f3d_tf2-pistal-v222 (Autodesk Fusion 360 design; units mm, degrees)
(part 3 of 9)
sketch "Sketch46" plane through (0, 19.0955, 0) normal (0, -1, 0) x axis (1, 0, 0)
  line L1 (17.9977, -3.324) -> (-17.9973, -3.324)
  line L2 (17.9977, -3.324) -> (19.9977, 0.985)
  line L3 (19.9977, 30) -> (19.9977, 0.985)
  line L4 (-19.9973, 30) -> (19.9977, 30)
  line L5 (-19.9973, 0.985) -> (-19.9973, 30)
  line L6 (-19.9973, 0.985) -> (-17.9973, -3.324)
  line L7 (-15, 25) -> (15, 25)
  line L8 (-15, -25) -> (-15, 25)
  line L9 (15, -25) -> (-15, -25)
  line L10 (15, 25) -> (15, -25)
  line L11 (-15, -25) -> (15, 25)
  line L12 (15, -25) -> (-15, 25)
  line L13 (-18.3388, 10) -> (-9.0048, 10)
  line L14 (-19.9973, 10) -> (-18.3388, 10)
  line L15 (-19.9973, 10) -> (-19.9977, 10)
  line L16 (-13, 10) -> (-19.9977, 10)
  line L17 (-9.0048, 10) -> (-13, 10)
  line L18 (40, 10) -> (-30, 10)
  point P12 (0, 0)
  point P1 (0, 0)
  horizontal L7
  perpendicular L7 L8
  parallel L7 L9
  parallel L8 L10
  coincident L11 P12
  coincident L12 P12
  coincident P1 P12
  perpendicular L5 L18
extrude "Extrude43" cut sketch "Sketch46" profile of L3 L4 L5 L7 L8 L10 L13 L14 L16 L18 against normal blind 125.217
delete_face "DeleteFace39"
extrude "Extrude44" add of existing geometry blind 3
fillet "Fillet54" radius 12
move "Move19" RotateAngle 30
sketch "Sketch47" plane through (16.9981, 0, 0) normal (1, 0, 0) x axis (0, 1, 0)
  line L1 (175.396, -38.6118) -> (173.8866, -33.2249)
  curve K1 (175.4894, -38.6471) -> (175.396, -38.6118)
  curve K2 (175.2557, -36.9411) -> (175.8993, -38.2372)
  curve K3 (175.7658, -36.3594) -> (175.2557, -36.9411)
  curve K4 (177.1348, -36.8283) -> (175.7658, -36.3594)
  curve K5 (176.6805, -35.1674) -> (177.4877, -36.3684)
  curve K6 (177.1103, -34.5242) -> (176.6805, -35.1674)
  curve K7 (178.5288, -34.8104) -> (177.1103, -34.5242)
  curve K8 (177.8615, -33.223) -> (178.8186, -34.3083)
  curve K9 (178.2037, -32.5291) -> (177.8615, -33.223)
  curve K10 (179.6474, -32.6277) -> (178.2037, -32.5291)
  curve K11 (178.7787, -31.141) -> (179.8693, -32.0922)
  curve K12 (179.0274, -30.4084) -> (178.7787, -31.141)
  curve K13 (180.4716, -30.3177) -> (179.0274, -30.4084)
  curve K14 (179.4162, -28.9571) -> (180.6216, -29.7578)
  curve K15 (179.5672, -28.1983) -> (179.4162, -28.9571)
  curve K16 (180.9872, -27.9199) -> (179.5672, -28.1983)
  curve K17 (179.7633, -26.7087) -> (181.0629, -27.3452)
  curve K18 (179.8139, -25.9367) -> (179.7633, -26.7087)
  curve K19 (181.1854, -25.4753) -> (179.8139, -25.9367)
  curve K20 (179.8139, -24.4342) -> (181.1854, -24.8956)
  curve K21 (179.7633, -23.6622) -> (179.8139, -24.4342)
  curve K22 (181.0629, -23.0257) -> (179.7633, -23.6622)
  curve K23 (179.5672, -22.1726) -> (180.9872, -22.451)
  curve K24 (179.4162, -21.4138) -> (179.5672, -22.1726)
  curve K25 (180.6216, -20.6131) -> (179.4162, -21.4138)
  curve K26 (179.0274, -19.9625) -> (180.4716, -20.0532)
  curve K27 (178.7787, -19.2299) -> (179.0274, -19.9625)
  curve K28 (179.8693, -18.2788) -> (178.7787, -19.2299)
  curve K29 (178.2037, -17.8418) -> (179.6474, -17.7432)
  curve K30 (177.8615, -17.148) -> (178.2037, -17.8418)
  curve K31 (178.8186, -16.0626) -> (177.8615, -17.148)
  curve K32 (177.1103, -15.8468) -> (178.5288, -15.5606)
  curve K33 (176.6805, -15.2035) -> (177.1103, -15.8468)
  curve K34 (177.4877, -14.0025) -> (176.6805, -15.2035)
  curve K35 (175.7658, -14.0115) -> (177.1348, -13.5426)
  curve K36 (175.2557, -13.4298) -> (175.7658, -14.0115)
  curve K37 (175.8993, -12.1337) -> (175.2557, -13.4298)
  curve K38 (174.1933, -12.3674) -> (175.4894, -11.7239)
  curve K39 (173.6116, -11.8573) -> (174.1933, -12.3674)
  curve K40 (174.0805, -10.4883) -> (173.6116, -11.8573)
  curve K41 (172.4196, -10.9427) -> (173.6206, -10.1354)
  curve K42 (171.9212, -10.9679) -> (172.4196, -10.9427)
  line L2 (170.1162, -13.6698) -> (171.9212, -10.9679)
  line L3 (174.9197, -19.1688) -> (177.7876, -17.6663)
  arc A1 centre (162.4377, -25.1855) radius 18.75 clockwise from (175.8993, -38.2372) to (175.4894, -38.6471)
  arc A2 centre (162.4377, -25.1855) radius 18.75 clockwise from (177.4877, -36.3684) to (177.1348, -36.8283)
  arc A3 centre (162.4377, -25.1855) radius 18.75 clockwise from (178.8186, -34.3083) to (178.5288, -34.8104)
  arc A4 centre (162.4377, -25.1855) radius 18.75 clockwise from (179.8693, -32.0922) to (179.6474, -32.6277)
  arc A5 centre (162.4377, -25.1855) radius 18.75 clockwise from (180.6216, -29.7578) to (180.4716, -30.3177)
  arc A6 centre (162.4377, -25.1855) radius 18.75 clockwise from (181.0629, -27.3452) to (180.9872, -27.9199)
  arc A7 centre (162.4377, -25.1855) radius 18.75 clockwise from (181.1854, -24.8956) to (181.1854, -25.4753)
  arc A8 centre (162.4377, -25.1855) radius 18.75 clockwise from (180.9872, -22.451) to (181.0629, -23.0257)
  arc A9 centre (162.4377, -25.1855) radius 18.75 clockwise from (180.4716, -20.0532) to (180.6216, -20.6131)
  arc A10 centre (162.4377, -25.1855) radius 18.75 clockwise from (179.6474, -17.7432) to (179.8693, -18.2788)
  arc A11 centre (162.4377, -25.1855) radius 18.75 clockwise from (178.5288, -15.5606) to (178.8186, -16.0626)
  arc A12 centre (162.4377, -25.1855) radius 18.75 clockwise from (177.1348, -13.5426) to (177.4877, -14.0025)
  arc A13 centre (162.4377, -25.1855) radius 18.75 clockwise from (175.4894, -11.7239) to (175.8993, -12.1337)
  arc A14 centre (162.4377, -25.1855) radius 18.75 clockwise from (173.6206, -10.1354) to (174.0805, -10.4883)
  arc A15 centre (162.3398, -25.3102) radius 13.999 clockwise from (170.1162, -13.6698) to (173.8866, -33.2249)
  point P63 (177.7876, -17.6663)
  point P64 (174.9197, -19.1688)
  coincident K30 P63
  coincident A15 P64
extrude "Extrude45" new body sketch "Sketch47" profile of K30 K31 A11 K32 K33 K34 A12 K35 K36 K37 A13 K38 K39 K40 A14 K41 K42 L2 A15 L3 against normal blind 4
mirror "Mirror16" mirrorStitchTolerance 0.1
combine "Combine40"
fillet "Fillet55" radius 2
revolve "Revolve1" AlongAngle 30
revolve "Revolve2" AlongAngle 30
move "Move20" RotateAngle -30
sketch "Circle" plane through (16.7981, 0, 0) normal (1, 0, 0) x axis (0, 1, 0)
  line L1 (189.7947, -21.9467) -> (189.6413, -21.8116)
  curve K1 (190.953, -22.2857) -> (189.7947, -21.9467)
  curve K2 (190.5246, -20.9044) -> (191.2393, -21.8768)
  line L2 (190.3451, -20.8065) -> (190.5246, -20.9044)
  line L3 (190.9023, -20.0459) -> (190.7088, -19.9798)
  curve K3 (192.1021, -19.9159) -> (190.9023, -20.0459)
  curve K4 (191.1777, -18.8037) -> (192.2101, -19.4286)
  line L4 (190.9744, -18.7819) -> (191.1777, -18.8037)
  line L5 (191.1981, -17.866) -> (190.9941, -17.879)
  curve K5 (192.2569, -17.2868) -> (191.1981, -17.866)
  curve K6 (190.9772, -16.6129) -> (192.1702, -16.7952)
  line L6 (190.7811, -16.6706) -> (190.9772, -16.6129)
  line L7 (190.6373, -15.7388) -> (190.4537, -15.8288)
  curve K7 (191.3937, -14.7985) -> (190.6373, -15.7388)
  curve K8 (189.9536, -14.6657) -> (191.1255, -14.3775)
  line L8 (189.7944, -14.794) -> (189.9536, -14.6657)
  line L9 (189.305, -13.9882) -> (189.1699, -14.1416)
  curve K9 (189.6441, -12.8299) -> (189.305, -13.9882)
  curve K10 (188.2628, -13.2584) -> (189.2352, -12.5436)
  line L10 (188.1648, -13.4378) -> (188.2628, -13.2584)
  line L11 (187.4043, -12.8806) -> (187.3382, -13.0741)
  curve K11 (187.2743, -11.6808) -> (187.4043, -12.8806)
  curve K12 (186.162, -12.6052) -> (186.7869, -11.5728)
  line L12 (186.1402, -12.8085) -> (186.162, -12.6052)
  line L13 (185.2244, -12.5848) -> (185.2373, -12.7888)
  curve K13 (184.6451, -11.526) -> (185.2244, -12.5848)
  curve K14 (183.9713, -12.8057) -> (184.1535, -11.6127)
  line L14 (184.0289, -13.0019) -> (183.9713, -12.8057)
  line L15 (183.0972, -13.1457) -> (183.1872, -13.3292)
  curve K15 (182.1568, -12.3892) -> (183.0972, -13.1457)
  curve K16 (182.024, -13.8293) -> (181.7358, -12.6574)
  line L16 (182.1523, -13.9885) -> (182.024, -13.8293)
  line L17 (181.3465, -14.4779) -> (181.5, -14.613)
  curve K17 (180.1883, -14.1388) -> (181.3465, -14.4779)
  curve K18 (180.6167, -15.5202) -> (179.902, -14.5477)
  line L18 (180.7962, -15.6181) -> (180.6167, -15.5202)
  line L19 (180.239, -16.3786) -> (180.4324, -16.4448)
  curve K19 (179.0392, -16.5087) -> (180.239, -16.3786)
  curve K20 (179.9636, -17.6209) -> (178.9311, -16.996)
  line L20 (180.1668, -17.6427) -> (179.9636, -17.6209)
  line L21 (179.9431, -18.5586) -> (180.1471, -18.5456)
  curve K21 (178.8844, -19.1378) -> (179.9431, -18.5586)
  curve K22 (180.1641, -19.8116) -> (178.9711, -19.6294)
  line L22 (180.3602, -19.754) -> (180.1641, -19.8116)
  line L23 (180.504, -20.6858) -> (180.6875, -20.5957)
  curve K23 (179.7475, -21.6261) -> (180.504, -20.6858)
  curve K24 (181.1877, -21.7589) -> (180.0157, -22.0471)
  line L24 (181.3468, -21.6306) -> (181.1877, -21.7589)
  line L25 (181.8362, -22.4364) -> (181.9714, -22.283)
  curve K25 (181.4972, -23.5946) -> (181.8362, -22.4364)
  curve K26 (182.8785, -23.1662) -> (181.9061, -23.8809)
  line L26 (182.9765, -22.9868) -> (182.8785, -23.1662)
  line L27 (183.737, -23.5439) -> (183.8031, -23.3505)
  curve K27 (183.867, -24.7438) -> (183.737, -23.5439)
  curve K28 (184.9792, -23.8193) -> (184.3543, -24.8518)
  line L28 (185.0011, -23.6161) -> (184.9792, -23.8193)
  line L29 (185.9169, -23.8398) -> (185.904, -23.6358)
  curve K29 (186.4962, -24.8985) -> (185.9169, -23.8398)
  curve K30 (187.17, -23.6188) -> (186.9877, -24.8119)
  line L30 (187.1123, -23.4227) -> (187.17, -23.6188)
  line L31 (188.0441, -23.2789) -> (187.9541, -23.0954)
  curve K31 (188.9844, -24.0354) -> (188.0441, -23.2789)
  curve K32 (189.1172, -22.5953) -> (189.4054, -23.7672)
  line L32 (188.9889, -22.4361) -> (189.1172, -22.5953)
  line L33 (185.5706, -18.2123) -> (187.0316, -11.6223)
  line L34 (178.9232, -19.3844) -> (185.5706, -18.2123)
  line L35 (195.7076, 27.5124) -> (187.0316, -11.6223)
  line L36 (129.6, -28.0814) -> (178.9232, -19.3844)
  circle C1 centre (185.5706, -18.2123) radius 2.5
  arc A1 centre (185.5706, -18.2123) radius 6.75 clockwise from (191.2393, -21.8768) to (190.953, -22.2857)
  arc A2 centre (190.5368, -20.4554) radius 0.4 clockwise from (190.3451, -20.8065) to (190.1722, -20.2907)
  arc A3 centre (185.5706, -18.2123) radius 5.0492 clockwise from (190.2118, -20.2008) to (190.1722, -20.2907)
  arc A4 centre (190.5795, -20.3583) radius 0.4 clockwise from (190.2118, -20.2008) to (190.7088, -19.9798)
  arc A5 centre (185.5706, -18.2123) radius 6.75 clockwise from (192.2101, -19.4286) to (192.1021, -19.9159)
  arc A6 centre (191.0171, -18.3842) radius 0.4 clockwise from (190.9744, -18.7819) to (190.6173, -18.3715)
  arc A7 centre (185.5706, -18.2123) radius 5.0492 clockwise from (190.6195, -18.2733) to (190.6173, -18.3715)
  arc A8 centre (191.0194, -18.2782) radius 0.4 clockwise from (190.6195, -18.2733) to (190.9941, -17.879)
  arc A9 centre (185.5706, -18.2123) radius 6.75 clockwise from (192.1702, -16.7952) to (192.2569, -17.2868)
  arc A10 centre (190.6683, -16.2868) radius 0.4 clockwise from (190.7811, -16.6706) to (190.2941, -16.4281)
  arc A11 centre (185.5706, -18.2123) radius 5.0492 clockwise from (190.2585, -16.3366) to (190.2941, -16.4281)
  arc A12 centre (190.6299, -16.188) radius 0.4 clockwise from (190.2585, -16.3366) to (190.4537, -15.8288)
  arc A13 centre (185.5706, -18.2123) radius 6.75 clockwise from (191.1255, -14.3775) to (191.3937, -14.7985)
  arc A14 centre (189.5434, -14.4826) radius 0.4 clockwise from (189.7944, -14.794) to (189.2518, -14.7563)
  arc A15 centre (185.5706, -18.2123) radius 5.0492 clockwise from (189.1839, -14.6854) to (189.2518, -14.7563)
  arc A16 centre (189.4701, -14.406) radius 0.4 clockwise from (189.1839, -14.6854) to (189.1699, -14.1416)
  arc A17 centre (185.5706, -18.2123) radius 6.75 clockwise from (189.2352, -12.5436) to (189.6441, -12.8299)
  arc A18 centre (187.8137, -13.2462) radius 0.4 clockwise from (188.1648, -13.4378) to (187.649, -13.6107)
  arc A19 centre (185.5706, -18.2123) radius 5.0492 clockwise from (187.5591, -13.5711) to (187.649, -13.6107)
  arc A20 centre (187.7167, -13.2035) radius 0.4 clockwise from (187.5591, -13.5711) to (187.3382, -13.0741)
  arc A21 centre (185.5706, -18.2123) radius 6.75 clockwise from (186.7869, -11.5728) to (187.2743, -11.6808)
  arc A22 centre (185.7425, -12.7658) radius 0.4 clockwise from (186.1402, -12.8085) to (185.7299, -13.1656)
  arc A23 centre (185.5706, -18.2123) radius 5.0492 clockwise from (185.6317, -13.1635) to (185.7299, -13.1656)
  arc A24 centre (185.6365, -12.7635) radius 0.4 clockwise from (185.6317, -13.1635) to (185.2373, -12.7888)
  arc A25 centre (185.5706, -18.2123) radius 6.75 clockwise from (184.1535, -11.6127) to (184.6451, -11.526)
  arc A26 centre (183.6451, -13.1146) radius 0.4 clockwise from (184.0289, -13.0019) to (183.7865, -13.4888)
  arc A27 centre (185.5706, -18.2123) radius 5.0492 clockwise from (183.6949, -13.5244) to (183.7865, -13.4888)
  arc A28 centre (183.5463, -13.153) radius 0.4 clockwise from (183.6949, -13.5244) to (183.1872, -13.3292)
  arc A29 centre (185.5706, -18.2123) radius 6.75 clockwise from (181.7358, -12.6574) to (182.1568, -12.3892)
  arc A30 centre (181.8409, -14.2395) radius 0.4 clockwise from (182.1523, -13.9885) to (182.1147, -14.5311)
  arc A31 centre (185.5706, -18.2123) radius 5.0492 clockwise from (182.0437, -14.5991) to (182.1147, -14.5311)
  arc A32 centre (181.7643, -14.3128) radius 0.4 clockwise from (182.0437, -14.5991) to (181.5, -14.613)
  arc A33 centre (185.5706, -18.2123) radius 6.75 clockwise from (179.902, -14.5477) to (180.1883, -14.1388)
  arc A34 centre (180.6045, -15.9692) radius 0.4 clockwise from (180.7962, -15.6181) to (180.969, -16.1339)
  arc A35 centre (185.5706, -18.2123) radius 5.0492 clockwise from (180.9295, -16.2238) to (180.969, -16.1339)
  arc A36 centre (180.5618, -16.0663) radius 0.4 clockwise from (180.9295, -16.2238) to (180.4324, -16.4448)
  arc A37 centre (185.5706, -18.2123) radius 6.75 clockwise from (178.9311, -16.996) to (179.0392, -16.5087)
  arc A38 centre (180.1241, -18.0404) radius 0.4 clockwise from (180.1668, -17.6427) to (180.5239, -18.053)
  arc A39 centre (185.5706, -18.2123) radius 5.0492 clockwise from (180.5218, -18.1513) to (180.5239, -18.053)
  arc A40 centre (180.1218, -18.1464) radius 0.4 clockwise from (180.5218, -18.1513) to (180.1471, -18.5456)
  arc A41 centre (185.5706, -18.2123) radius 6.75 clockwise from (178.9711, -19.6294) to (178.8844, -19.1378)
  arc A42 centre (180.473, -20.1378) radius 0.4 clockwise from (180.3602, -19.754) to (180.8472, -19.9964)
  arc A43 centre (185.5706, -18.2123) radius 5.0492 clockwise from (180.8828, -20.088) to (180.8472, -19.9964)
  arc A44 centre (180.5114, -20.2366) radius 0.4 clockwise from (180.8828, -20.088) to (180.6875, -20.5957)
  arc A45 centre (185.5706, -18.2123) radius 6.75 clockwise from (180.0157, -22.0471) to (179.7475, -21.6261)
  arc A46 centre (181.5979, -21.942) radius 0.4 clockwise from (181.3468, -21.6306) to (181.8895, -21.6682)
  arc A47 centre (185.5706, -18.2123) radius 5.0492 clockwise from (181.9574, -21.7392) to (181.8895, -21.6682)
  arc A48 centre (181.6712, -22.0186) radius 0.4 clockwise from (181.9574, -21.7392) to (181.9714, -22.283)
  arc A49 centre (185.5706, -18.2123) radius 6.75 clockwise from (181.9061, -23.8809) to (181.4972, -23.5946)
  arc A50 centre (183.3276, -23.1784) radius 0.4 clockwise from (182.9765, -22.9868) to (183.4922, -22.8139)
  arc A51 centre (185.5706, -18.2123) radius 5.0492 clockwise from (183.5821, -22.8534) to (183.4922, -22.8139)
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  point P163 (187.0316, -11.6223)
  point P2 (185.5706, -18.2123)
  point P164 (185.5706, -18.2123)
  point P165 (178.9232, -19.3844)
  point P168 (185.5706, -18.2123)
  midpoint A21 P163
  coincident P2 P164
  midpoint A41 P165
  parallel L33 L35
  parallel L34 L36
  coincident P164 P168
sketch "Stroke" plane through (3.8654, 0, 0) normal (1, 0, 0) x axis (0, 1, 0)
  line L1 (212.982, 13.4446) -> (169.981, 13.4446)
  line L2 (212.982, 27.7788) -> (212.982, 13.4446)
  line L3 (173.082, 27.7788) -> (212.982, 27.7788)
  line L4 (169.982, 24.6788) -> (173.082, 27.7788)
  line L5 (169.982, 24.6413) -> (169.982, 24.6788)
  line L6 (169.981, 24.6413) -> (169.982, 24.6413)
  line L7 (169.981, 13.4446) -> (169.981, 24.6413)
  line L8 (152.982, 24.7645) -> (152.982, 13.2652)
  line L9 (84.482, 19.0149) -> (152.982, 19.0149)
  line L10 (84.482, 32) -> (84.482, 19.0149)
  line L11 (152.982, 32) -> (84.482, 32)
  line L12 (152.982, 19.0149) -> (152.982, 32)
  point P11 (152.982, 19.0149)
  point P13 (84.482, 32)
  point P14 (152.982, 32)
  horizontal L9
  vertical L10
  horizontal L11
  vertical L12
  midpoint L8 P11
  dimension "d384" distance P13 P14 = 68.5
remove_body "RemoveBody8"
chamfer "Chamfer12" distance 2
sketch "Sketch50" plane through (-19.9977, 0, 0) normal (1, 0, 0) x axis (0, 1, 0)
  line L1 (196.128, -152.4983) -> (196.128, -141.5431)
  line L2 (197.0728, -155.7059) -> (196.128, -152.4983)
  line L3 (251.8597, -142.3998) -> (202.8089, -158.7048)
  line L4 (221.8838, -55.9408) -> (254.6088, -136.4348)
  line L5 (221.8838, -21.4864) -> (221.8838, -55.9408)
  line L6 (162.8556, -14.4864) -> (214.8838, -14.4864)
  line L7 (196.128, -141.5431) -> (156.2255, -23.732)
  line L8 (184.5414, -86.2118) -> (208.6976, -158.8816)
  curve K1 (191.5411, -158.0426) -> (200.3787, -135.1036)
  line L9 (200.3787, -133.8556) -> (200.3787, -135.1036)
  arc A1 centre (201.3894, -154.4345) radius 4.5 clockwise from (202.8089, -158.7048) to (197.0728, -155.7059)
  arc A2 centre (250.4402, -138.1296) radius 4.5 clockwise from (254.6088, -136.4348) to (251.8597, -142.3998)
  arc A3 centre (214.8838, -21.4864) radius 7 clockwise from (214.8838, -14.4864) to (221.8838, -21.4864)
  arc A4 centre (162.8556, -21.4864) radius 7 clockwise from (156.2255, -23.732) to (162.8556, -14.4864)
  arc A5 centre (156.0731, -95.675) radius 30 clockwise from (159.0691, -65.8249) to (184.5414, -86.2118)
  point P21 (200.3787, -135.1036)
  point P23 (200.3787, -135.1036)
  point P24 (200.3787, -133.8556)
  coincident P21 P23
  coincident L8 P24
  vertical L9
extrude "Extrude46" new body sketch "Sketch50" profile of L1 L2 L7 A5 L8 K1 L9 along normal blind 1.5
fillet "Fillet56" radius 0.1
fillet "Fillet57" radius 0.15
fillet "Fillet58" radius 0.35
offset_faces "OffsetFaces5" distance 0.5
move_face "MoveFace50" TranslateX -2 TranslateY 0 TranslateZ 0
move_face "MoveFace51" TranslateX 2 TranslateY 0 TranslateZ 0
move_face "MoveFace52"
move_face "MoveFace53"
delete_face "DeleteFace40"
fillet "Fillet59" radius 0.25
move_face "MoveFace54"
mirror "Mirror17" mirrorStitchTolerance 0.1
combine "Combine41"
combine "Combine42"
move_face "MoveFace55"
fillet "Fillet60" radius 1
move "Move21" RotateAngle 30
sketch "Sketch51" plane through (19.9977, 0, 0) normal (1, 0, 0) x axis (0, 1, 0)
  line L1 (155.774, -64.8873) -> (153.2868, -55.2709)
  line L2 (158.6388, -64.1463) -> (155.774, -64.8873)
  line L3 (159.119, -65.3274) -> (158.6388, -64.1463)
  line L4 (209.1721, -158.7239) -> (185.0159, -86.0541)
  line L5 (255.6377, -143.2782) -> (209.1721, -158.7239)
  line L6 (209.6429, -30.1443) -> (255.6377, -143.2782)
  curve K1 (209.4603, -30.1452) -> (209.6429, -30.1443)
  line L7 (144.1511, -30.1452) -> (209.4603, -30.1452)
  line L8 (153.3896, -51.2349) -> (153.3078, -51.0336)
  curve K2 (153.2868, -55.2709) -> (153.3896, -51.2349)
  curve K3 (148.3921, -52.2184) -> (146.2926, -63.0126)
  curve K4 (136.1286, -29.6952) -> (114.0506, -76.7116)
  line L9 (136.1286, -29.6952) -> (136.7565, -29.9764)
  curve K5 (146.2926, -63.0126) -> (131.2611, -28.0265)
  arc A1 centre (156.0731, -95.675) radius 30.5 clockwise from (159.119, -65.3274) to (185.0159, -86.0541)
  arc A2 centre (116.7403, -54.6121) radius 36.7422 clockwise from (144.1511, -30.1452) to (153.3078, -51.0336)
  arc A3 centre (116.7403, -54.6121) radius 31.7422 clockwise from (136.7565, -29.9764) to (148.3921, -52.2184)
  point P17 (136.7565, -29.9764)
  point P22 (136.7565, -29.9764)
  point P21 (136.1286, -29.6952)
  point P23 (136.1286, -29.6952)
  point P24 (131.2611, -28.0265)
  point P19 (146.2926, -63.0126)
  point P27 (146.2926, -63.0126)
  coincident P17 P22
  coincident P21 P23
  coincident K4 P24
  coincident P19 P27
extrude "Extrude47" new body sketch "Sketch51" profile of A3 K3 K4 L9 K5 against normal blind 20 and against normal blind 12
fillet "Fillet61" radius 4
fillet "Fillet62" radius 0.5
mirror "Mirror18" mirrorStitchTolerance 0.1
move "Move22" RotateAngle 5
move "Move23" RotateAngle 1
copy_paste_bodies "CopyPasteBodies3"
move "Move24" TranslateX 0 TranslateY 0 TranslateZ 72
move "Move25" RotateAngle 4.5
sketch "Sketch52" plane through (12.7981, 0, 0) normal (1, 0, 0) x axis (0, 1, 0)
  line L1 (189.2308, 49.4991) -> (189.0983, 49.6548)
  curve K1 (189.5495, 48.3351) -> (189.2308, 49.4991)
  curve K2 (188.1759, 48.7876) -> (189.1357, 48.056)
  line L2 (188.0811, 48.9687) -> (188.1759, 48.7876)
  line L3 (187.311, 48.4249) -> (187.2482, 48.6194)
  curve K3 (187.16, 47.2275) -> (187.311, 48.4249)
  curve K4 (186.0641, 48.1712) -> (186.6709, 47.128)
  line L4 (186.0458, 48.3748) -> (186.0641, 48.1712)
  line L5 (185.1262, 48.1671) -> (185.1427, 48.3709)
  curve K5 (184.5286, 47.1186) -> (185.1262, 48.1671)
  curve K6 (183.8772, 48.4099) -> (184.0386, 47.2139)
  line L6 (183.9382, 48.605) -> (183.8772, 48.4099)
  line L7 (183.0091, 48.765) -> (183.1023, 48.947)
  curve K7 (182.0557, 48.0251) -> (183.0091, 48.765)
  curve K8 (181.9481, 49.4673) -> (181.6395, 48.3006)
  line L8 (182.0791, 49.6242) -> (181.9481, 49.4673)
  line L9 (181.282, 50.1276) -> (181.4378, 50.26)
  curve K9 (180.118, 49.8088) -> (181.282, 50.1276)
  curve K10 (180.5705, 51.1825) -> (179.8389, 50.2227)
  line L10 (180.7516, 51.2773) -> (180.5705, 51.1825)
  line L11 (180.2078, 52.0474) -> (180.4024, 52.1101)
  curve K11 (179.0104, 52.1983) -> (180.2078, 52.0474)
  curve K12 (179.9541, 53.2943) -> (178.9109, 52.6875)
  line L12 (180.1577, 53.3125) -> (179.9541, 53.2943)
  line L13 (179.95, 54.2321) -> (180.1538, 54.2156)
  curve K13 (178.9016, 54.8298) -> (179.95, 54.2321)
  curve K14 (180.1928, 55.4812) -> (178.9968, 55.3198)
  line L14 (180.3879, 55.4201) -> (180.1928, 55.4812)
  line L15 (180.5479, 56.3492) -> (180.7299, 56.256)
  curve K15 (179.808, 57.3026) -> (180.5479, 56.3492)
  curve K16 (181.2502, 57.4103) -> (180.0835, 57.7189)
  line L16 (181.4071, 57.2792) -> (181.2502, 57.4103)
  line L17 (181.9105, 58.0763) -> (182.0429, 57.9206)
  curve K17 (181.5918, 59.2403) -> (181.9105, 58.0763)
  curve K18 (182.9654, 58.7879) -> (182.0056, 59.5195)
  line L18 (183.0602, 58.6067) -> (182.9654, 58.7879)
  line L19 (183.8303, 59.1506) -> (183.8931, 58.956)
  curve K19 (183.9813, 60.3479) -> (183.8303, 59.1506)
  curve K20 (185.0772, 59.4042) -> (184.4704, 60.4474)
  line L20 (185.0954, 59.2006) -> (185.0772, 59.4042)
  line L21 (186.0151, 59.4083) -> (185.9986, 59.2046)
  curve K21 (186.6127, 60.4568) -> (186.0151, 59.4083)
  curve K22 (187.2641, 59.1655) -> (187.1027, 60.3615)
  line L22 (187.203, 58.9704) -> (187.2641, 59.1655)
  line L23 (188.1321, 58.8104) -> (188.0389, 58.6285)
  curve K23 (189.0855, 59.5503) -> (188.1321, 58.8104)
  curve K24 (189.1932, 58.1081) -> (189.5018, 59.2748)
  line L24 (189.0621, 57.9512) -> (189.1932, 58.1081)
  line L25 (189.8593, 57.4478) -> (189.7035, 57.3154)
  curve K25 (191.0232, 57.7666) -> (189.8593, 57.4478)
  curve K26 (190.5708, 56.393) -> (191.3024, 57.3528)
  line L26 (190.3897, 56.2982) -> (190.5708, 56.393)
  line L27 (190.9335, 55.528) -> (190.7389, 55.4653)
  curve K27 (192.1308, 55.3771) -> (190.9335, 55.528)
  curve K28 (191.1872, 54.2812) -> (192.2304, 54.888)
  line L28 (190.9835, 54.2629) -> (191.1872, 54.2812)
  line L29 (191.1912, 53.3433) -> (190.9875, 53.3598)
  curve K29 (192.2397, 52.7456) -> (191.1912, 53.3433)
  curve K30 (190.9485, 52.0943) -> (192.1445, 52.2556)
  line L30 (190.7534, 52.1553) -> (190.9485, 52.0943)
  line L31 (190.5933, 51.2262) -> (190.4114, 51.3194)
  curve K31 (191.3333, 50.2728) -> (190.5933, 51.2262)
  curve K32 (189.891, 50.1652) -> (191.0578, 49.8566)
  line L32 (189.7341, 50.2962) -> (189.891, 50.1652)
  line L33 (183.7389, 20.0084) -> (183.7654, 20.503)
  curve K33 (185.5183, 14.7877) -> (183.7389, 20.0084)
  curve K34 (189.1678, 20.1506) -> (187.664, 14.8439)
  line L34 (189.1154, 20.6431) -> (189.1678, 20.1506)
  line L35 (192.544, 20.6853) -> (192.4417, 21.1699)
  curve K35 (195.614, 16.1031) -> (192.544, 20.6853)
  curve K36 (197.7511, 22.2277) -> (197.672, 16.7127)
  line L36 (197.573, 22.6899) -> (197.7511, 22.2277)
  line L37 (200.8739, 23.6181) -> (200.6496, 24.0597)
  curve K37 (205.0253, 19.9866) -> (200.8739, 23.6181)
  curve K38 (205.5044, 26.4557) -> (206.8554, 21.1081)
  line L38 (205.2128, 26.856) -> (205.5044, 26.4557)
  line L39 (208.161, 28.6069) -> (207.83, 28.9754)
  curve K39 (213.1108, 26.1736) -> (208.161, 28.6069)
  curve K40 (211.8992, 32.5462) -> (214.5883, 27.7305)
  line L40 (211.5139, 32.8574) -> (211.8992, 32.5462)
  line L41 (213.9085, 35.3117) -> (213.4935, 35.582)
  curve K41 (219.3194, 34.2424) -> (213.9085, 35.3117)
  curve K42 (216.4998, 40.0843) -> (220.3436, 36.1287)
  line L42 (216.0471, 40.2852) -> (216.4998, 40.0843)
  line L43 (217.7248, 43.2756) -> (217.254, 43.4293)
  curve K43 (223.2282, 43.6433) -> (217.7248, 43.2756)
  curve K44 (218.9926, 48.5563) -> (223.7292, 45.7303)
  line L44 (218.5033, 48.6332) -> (218.9926, 48.5563)
  line L45 (219.3499, 51.956) -> (218.8554, 51.9825)
  curve K45 (224.5706, 53.7354) -> (219.3499, 51.956)
  curve K46 (219.2078, 57.3848) -> (224.5144, 55.8811)
  line L46 (218.7153, 57.3324) -> (219.2078, 57.3848)
  line L47 (218.673, 60.7611) -> (218.1884, 60.6587)
  curve K47 (223.2552, 63.8311) -> (218.673, 60.7611)
  curve K48 (217.1306, 65.9682) -> (222.6456, 65.8891)
  line L48 (216.6685, 65.7901) -> (217.1306, 65.9682)
  line L49 (215.7403, 69.091) -> (215.2987, 68.8667)
  curve K49 (219.3718, 73.2424) -> (215.7403, 69.091)
  curve K50 (212.9027, 73.7215) -> (218.2503, 75.0725)
  line L50 (212.5024, 73.4299) -> (212.9027, 73.7215)
  line L51 (210.7515, 76.378) -> (210.383, 76.0471)
  curve K51 (213.1848, 81.3279) -> (210.7515, 76.378)
  curve K52 (206.8121, 80.1163) -> (211.6278, 82.8053)
  line L52 (206.5009, 79.731) -> (206.8121, 80.1163)
  line L53 (204.0466, 82.1256) -> (203.7764, 81.7105)
  curve K53 (205.1159, 87.5365) -> (204.0466, 82.1256)
  curve K54 (199.274, 84.7169) -> (203.2296, 88.5607)
  line L54 (199.0731, 84.2642) -> (199.274, 84.7169)
  line L55 (196.0827, 85.9419) -> (195.9291, 85.4711)
  curve K55 (195.7151, 91.4452) -> (196.0827, 85.9419)
  curve K56 (190.802, 87.2097) -> (193.628, 91.9463)
  line L56 (190.7252, 86.7204) -> (190.802, 87.2097)
  line L57 (187.4024, 87.567) -> (187.3758, 87.0725)
  curve K57 (185.6229, 92.7877) -> (187.4024, 87.567)
  curve K58 (181.9735, 87.4249) -> (183.4773, 92.7315)
  line L58 (182.0259, 86.9324) -> (181.9735, 87.4249)
  line L59 (178.5973, 86.8901) -> (178.6996, 86.4055)
  curve K59 (175.5272, 91.4723) -> (178.5973, 86.8901)
  curve K60 (173.3901, 85.3477) -> (173.4692, 90.8627)
  line L60 (173.5682, 84.8855) -> (173.3901, 85.3477)
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  point P407 (185.7528, 14.1364)
  point P411 (185.7528, 14.1364)
  coincident P407 P411
move "Move26" RotateAngle 1
move_face "MoveFace56" RotateAngle 1
move "Move27" RotateAngle 1
move "Move28" RotateAngle 0.5
move "Move29" RotateAngle 0.5
sketch "Sketch53" plane through (12.7981, 0, 0) normal (1, 0, 0) x axis (0, 1, 0)
  line L1 (189.1172, 49.4047) -> (188.9889, 49.5639)
  curve K1 (189.4054, 48.2328) -> (189.1172, 49.4047)
  curve K2 (188.0441, 48.7211) -> (188.9844, 47.9646)
  line L2 (187.9541, 48.9046) -> (188.0441, 48.7211)
  line L3 (187.17, 48.3812) -> (187.1123, 48.5773)
  curve K3 (186.9877, 47.1881) -> (187.17, 48.3812)
  curve K4 (185.9169, 48.1602) -> (186.4962, 47.1015)
  line L4 (185.904, 48.3642) -> (185.9169, 48.1602)
  line L5 (184.9792, 48.1807) -> (185.0011, 48.3839)
  curve K5 (184.3543, 47.1482) -> (184.9792, 48.1807)
  curve K6 (183.737, 48.4561) -> (183.867, 47.2562)
  line L6 (183.8031, 48.6495) -> (183.737, 48.4561)
  line L7 (182.8785, 48.8338) -> (182.9765, 49.0132)
  curve K7 (181.9061, 48.1191) -> (182.8785, 48.8338)
  curve K8 (181.8362, 49.5636) -> (181.4972, 48.4054)
  line L8 (181.9714, 49.717) -> (181.8362, 49.5636)
  line L9 (181.1877, 50.2411) -> (181.3468, 50.3694)
  curve K9 (180.0157, 49.9529) -> (181.1877, 50.2411)
  curve K10 (180.504, 51.3142) -> (179.7475, 50.3739)
  line L10 (180.6875, 51.4043) -> (180.504, 51.3142)
  line L11 (180.1641, 52.1884) -> (180.3602, 52.246)
  curve K11 (178.9711, 52.3706) -> (180.1641, 52.1884)
  curve K12 (179.9431, 53.4414) -> (178.8844, 52.8622)
  line L12 (180.1471, 53.4544) -> (179.9431, 53.4414)
  line L13 (179.9636, 54.3791) -> (180.1668, 54.3573)
  curve K13 (178.9311, 55.004) -> (179.9636, 54.3791)
  curve K14 (180.239, 55.6214) -> (179.0392, 55.4913)
  line L14 (180.4324, 55.5552) -> (180.239, 55.6214)
  line L15 (180.6167, 56.4798) -> (180.7962, 56.3819)
  curve K15 (179.902, 57.4523) -> (180.6167, 56.4798)
  curve K16 (181.3465, 57.5221) -> (180.1883, 57.8612)
  line L16 (181.5, 57.387) -> (181.3465, 57.5221)
  line L17 (182.024, 58.1707) -> (182.1523, 58.0115)
  curve K17 (181.7358, 59.3426) -> (182.024, 58.1707)
  curve K18 (183.0972, 58.8543) -> (182.1568, 59.6108)
  line L18 (183.1872, 58.6708) -> (183.0972, 58.8543)
  line L19 (183.9713, 59.1943) -> (184.0289, 58.9981)
  curve K19 (184.1535, 60.3873) -> (183.9713, 59.1943)
  curve K20 (185.2244, 59.4152) -> (184.6451, 60.474)
  line L20 (185.2373, 59.2112) -> (185.2244, 59.4152)
  line L21 (186.162, 59.3948) -> (186.1402, 59.1915)
  curve K21 (186.7869, 60.4272) -> (186.162, 59.3948)
  curve K22 (187.4043, 59.1194) -> (187.2743, 60.3192)
  line L22 (187.3382, 58.9259) -> (187.4043, 59.1194)
  line L23 (188.2628, 58.7416) -> (188.1648, 58.5622)
  curve K23 (189.2352, 59.4564) -> (188.2628, 58.7416)
  curve K24 (189.305, 58.0118) -> (189.6441, 59.1701)
  line L24 (189.1699, 57.8584) -> (189.305, 58.0118)
  line L25 (189.9536, 57.3343) -> (189.7944, 57.206)
  curve K25 (191.1255, 57.6225) -> (189.9536, 57.3343)
  curve K26 (190.6373, 56.2612) -> (191.3937, 57.2015)
  line L26 (190.4537, 56.1712) -> (190.6373, 56.2612)
  line L27 (190.9772, 55.3871) -> (190.7811, 55.3294)
  curve K27 (192.1702, 55.2048) -> (190.9772, 55.3871)
  curve K28 (191.1981, 54.134) -> (192.2569, 54.7132)
  line L28 (190.9941, 54.121) -> (191.1981, 54.134)
  line L29 (191.1777, 53.1963) -> (190.9744, 53.2181)
  curve K29 (192.2101, 52.5714) -> (191.1777, 53.1963)
  curve K30 (190.9023, 51.9541) -> (192.1021, 52.0841)
  line L30 (190.7088, 52.0202) -> (190.9023, 51.9541)
  line L31 (190.5246, 51.0956) -> (190.3451, 51.1935)
  curve K31 (191.2393, 50.1232) -> (190.5246, 51.0956)
  curve K32 (189.7947, 50.0533) -> (190.953, 49.7143)
  line L32 (189.6413, 50.1884) -> (189.7947, 50.0533)
  line L33 (182.8553, 20.0679) -> (182.8948, 20.5616)
  curve K33 (184.4974, 14.8025) -> (182.8553, 20.0679)
  curve K34 (188.286, 20.0679) -> (186.6438, 14.8025)
  line L34 (188.2465, 20.5616) -> (188.286, 20.0679)
  line L35 (191.6751, 20.5141) -> (191.5855, 21.0012)
  curve K35 (194.6241, 15.8531) -> (191.6751, 20.5141)
  curve K36 (196.9208, 21.9197) -> (196.6974, 16.4086)
  line L36 (196.7549, 22.3864) -> (196.9208, 21.9197)
  line L37 (200.0789, 23.2278) -> (199.8663, 23.6751)
  curve K37 (204.1338, 19.4889) -> (200.0789, 23.2278)
  curve K38 (204.7821, 25.9432) -> (205.9927, 20.5621)
  line L38 (204.5011, 26.351) -> (204.7821, 25.9432)
  line L39 (207.4941, 28.0242) -> (207.1729, 28.4012)
  curve K39 (212.3785, 25.4621) -> (207.4941, 28.0242)
  curve K40 (211.3342, 31.8643) -> (213.8962, 26.9799)
  line L40 (210.9572, 32.1855) -> (211.3342, 31.8643)
  line L41 (213.4151, 34.5762) -> (213.0073, 34.8573)
  curve K41 (218.7962, 33.3657) -> (213.4151, 34.5762)
  curve K42 (216.1305, 39.2794) -> (219.8694, 35.2245)
  line L42 (215.6832, 39.4921) -> (216.1305, 39.2794)
  line L43 (217.4387, 42.4375) -> (216.972, 42.6035)
  curve K43 (222.9497, 42.661) -> (217.4387, 42.4375)
  curve K44 (218.8442, 47.6832) -> (223.5052, 44.7342)
  line L44 (218.3571, 47.7729) -> (218.8442, 47.6832)
  line L45 (219.2904, 51.0723) -> (218.7967, 51.1118)
  curve K45 (224.5559, 52.7145) -> (219.2904, 51.0723)
  curve K46 (219.2904, 56.5031) -> (224.5559, 54.8609)
  line L46 (218.7967, 56.4636) -> (219.2904, 56.5031)
  line L47 (218.8442, 59.8922) -> (218.3571, 59.8026)
  curve K47 (223.5052, 62.8412) -> (218.8442, 59.8922)
  curve K48 (217.4387, 65.1379) -> (222.9497, 64.9145)
  line L48 (216.972, 64.972) -> (217.4387, 65.1379)
  line L49 (216.1305, 68.296) -> (215.6832, 68.0834)
  curve K49 (219.8694, 72.3509) -> (216.1305, 68.296)
  curve K50 (213.4151, 72.9992) -> (218.7962, 74.2097)
  line L50 (213.0073, 72.7181) -> (213.4151, 72.9992)
  line L51 (211.3342, 75.7111) -> (210.9572, 75.39)
  curve K51 (213.8962, 80.5956) -> (211.3342, 75.7111)
  curve K52 (207.4941, 79.5513) -> (212.3785, 82.1133)
  line L52 (207.1729, 79.1742) -> (207.4941, 79.5513)
  line L53 (204.7821, 81.6322) -> (204.5011, 81.2244)
  curve K53 (205.9927, 87.0133) -> (204.7821, 81.6322)
  curve K54 (200.0789, 84.3476) -> (204.1338, 88.0865)
  line L54 (199.8663, 83.9003) -> (200.0789, 84.3476)
  line L55 (196.9208, 85.6557) -> (196.7549, 85.1891)
  curve K55 (196.6974, 91.1668) -> (196.9208, 85.6557)
  curve K56 (191.6751, 87.0613) -> (194.6241, 91.7223)
  line L56 (191.5855, 86.5742) -> (191.6751, 87.0613)
  line L57 (188.286, 87.5075) -> (188.2465, 87.0138)
  curve K57 (186.6438, 92.7729) -> (188.286, 87.5075)
  curve K58 (182.8553, 87.5075) -> (184.4974, 92.7729)
  line L58 (182.8948, 87.0138) -> (182.8553, 87.5075)
  line L59 (179.4662, 87.0613) -> (179.5558, 86.5742)
  curve K59 (176.5171, 91.7223) -> (179.4662, 87.0613)
  curve K60 (174.2205, 85.6557) -> (174.4439, 91.1668)
  line L60 (174.3864, 85.1891) -> (174.2205, 85.6557)
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  point P401 (182.0081, 21.6353)
  point P403 (182.0081, 21.6353)
  point P169 (189.1332, 21.6353)
  point P404 (189.1332, 21.6353)
  coincident P401 P403
  coincident P169 P404
split "Split18"
remove_body "RemoveBody9"
remove_body "RemoveBody10"
remove_body "RemoveBody11"
remove_body "RemoveBody12"
remove_body "RemoveBody13"
move "Move30" RotateAngle -0.6
move "Move31" RotateAngle 0.1
move "Move32" RotateAngle -0.05
move "Move33" RotateAngle -0.05
move "Move34" RotateAngle 0.025
move "Move35" RotateAngle 0.01
move "Move36" RotateAngle 0.1
move "Move37" RotateAngle 0.1
move "Move38" RotateAngle 0.1
move "Move39" RotateAngle 0.05
move "Move40" RotateAngle 0.05
move "Move41" RotateAngle 0.1
move "Move42" RotateAngle 0.05
sketch "Sketch54" plane through (0, 144.3129, 0) normal (0, 1, 0) x axis (-1, 0, 0)
  line L1 (-3, 28) -> (3, 28)
  line L2 (-15, 10) -> (-15, 16)
  line L3 (-19.9977, 10) -> (-15, 10)
  line L4 (-19.9977, -29.2452) -> (-19.9977, 10)
  line L5 (-19.5477, -29.6952) -> (-19.9977, -29.2452)
  line L6 (19.5473, -29.6952) -> (-19.5477, -29.6952)
  line L7 (19.9973, -29.2452) -> (19.5473, -29.6952)
  line L8 (19.9973, 10) -> (19.9973, -29.2452)
  line L9 (15, 10) -> (19.9973, 10)
  line L10 (15, 16) -> (15, 10)
  line L11 (-4.4, 11.4743) -> (4.4, 11.4743)
  line L12 (4.4, 11.4743) -> (-4.4, 11.4743)
  line L13 (4.4, 9.1063) -> (4.4, 11.4743)
  line L14 (-4.4, 11.4743) -> (-4.4, 9.1063)
  line L15 (-4.4, -27.5283) -> (-4.4, 9.1063)
  line L16 (4.4, 9.1063) -> (4.4, -27.5283)
  line L17 (4.4, -29.6952) -> (4.4, -27.5283)
  line L18 (-4.4, -29.6952) -> (4.4, -29.6952)
  line L19 (-4.4, -27.5283) -> (-4.4, -29.6952)
  arc A1 centre (3, 16) radius 12 clockwise from (3, 28) to (15, 16)
  arc A2 centre (-3, 16) radius 12 clockwise from (-15, 16) to (-3, 28)
  point P17 (-4.4, 11.4743)
  point P18 (-4.4, 11.4743)
  point P26 (4.4, -29.6952)
  horizontal L12
  vertical L13
  vertical L14
  coincident P17 P18
  vertical L15
  vertical L16
  vertical L17
  horizontal L18
  vertical L19
  coincident L6 P26
extrude "Extrude48" new body sketch "Sketch54" profile of L6 L11 L12 L13 L14 L15 L16 L17 L18 L19 along normal blind 14
delete_face "DeleteFace41"
sketch "Sketch55" plane through (0, 144.3129, 0) normal (0, 1, 0) x axis (-1, 0, 0)
  line L1 (15, 28) -> (15, 10)
  line L2 (-15, 28) -> (15, 28)
  line L3 (-15, 10) -> (-15, 28)
  line L4 (-19.9977, 10) -> (-15, 10)
  line L5 (-19.9977, -29.2452) -> (-19.9977, 10)
  line L6 (-19.5477, -29.6952) -> (-19.9977, -29.2452)
  line L7 (19.5473, -29.6952) -> (-19.5477, -29.6952)
  line L8 (19.9973, -29.2452) -> (19.5473, -29.6952)
  line L9 (19.9973, 10) -> (19.9973, -29.2452)
  line L10 (15, 10) -> (19.9973, 10)
  line L11 (-5.6335, 23.5907) -> (-6.4544, 21.2774)
  line L12 (4.4, 11.4743) -> (-4.4, 11.4743)
  arc A1 centre (-0.116, 19.0281) radius 6.7256 clockwise from (-4.9991, 23.653) to (6.222, 21.2781)
  arc A2 centre (-0.116, 19.0281) radius 6.7256 clockwise from (6.222, 21.2781) to (-6.4544, 21.2774)
  circle C1 centre (-0.116, 19.0281) radius 7.5547
  concentric A1 C1
extrude "Extrude49" cut sketch "Sketch55" profile of L12 C1 against normal blind 190
sketch "Sketch56" plane through (0, 144.3129, 0) normal (0, 1, 0) x axis (-1, 0, 0)
  line L1 (-0.2321, 11.4743) -> (0, 11.4743)
  line L2 (15, 28) -> (15, 10)
  line L3 (-15, 28) -> (15, 28)
  line L4 (-15, 10) -> (-15, 28)
  line L5 (-19.9977, 10) -> (-15, 10)
  line L6 (-19.9977, -29.2452) -> (-19.9977, 10)
  line L7 (-19.5477, -29.6952) -> (-19.9977, -29.2452)
  line L8 (19.5473, -29.6952) -> (-19.5477, -29.6952)
  line L9 (19.9973, -29.2452) -> (19.5473, -29.6952)
  line L10 (19.9973, 10) -> (19.9973, -29.2452)
  line L11 (15, 10) -> (19.9973, 10)
  line L12 (4.4, 11.4743) -> (-4.4, 11.4743)
  line L13 (-4.4, 12.8055) -> (-4.4, 11.4743)
  line L14 (4.4, 12.9718) -> (4.4, 11.4743)
  arc A1 centre (-0.116, 19.0281) radius 7.5547 clockwise from (-0.2321, 11.4743) to (0, 11.4743)
  arc A2 centre (-0.116, 19.0281) radius 7.5547 clockwise from (-0.2321, 11.4743) to (0, 11.4743)
  point P15 (-4.4, 11.4743)
  point P20 (-4.4, 11.4743)
  point P21 (-4.4, 12.8055)
  point P16 (4.4, 11.4743)
  point P22 (4.4, 11.4743)
  point P23 (4.4, 12.9718)
  coincident P15 P20
  coincident A1 P21
  perpendicular L12 L13
  coincident P16 P22
  coincident A2 P23
  perpendicular L12 L14
extrude "Extrude50" new body sketch "Sketch56" profile of A1 L12 A2 L13 L14 along normal blind 14
combine "Combine43"
combine "Combine44"
fillet "Fillet63" radius 0.5
split "Split19"
move_face "MoveFace57"
combine "Combine45"
move_face "MoveFace58"
extrude "Extrude51" add of existing geometry blind 5
fillet "Fillet64" radius 2
move_face "MoveFace59"
fillet "Fillet65" radius 32.5
fillet "Fillet66" radius 10
move_face "MoveFace60" TranslateX 0 TranslateY 0 TranslateZ 2
fillet "Fillet67" radius 2.5
fillet "Fillet68" radius 1
combine "Combine46"
combine "Combine47"
offset_faces "OffsetFaces6" distance -0.2
offset_faces "OffsetFaces7" distance -0.2
sketch "Sketch57" plane through (15, 0, 0) normal (1, 0, 0) x axis (0, 1, 0)
  line L1 (158.3129, 30) -> (158.3129, 16.807)
  line L2 (19.0955, 30) -> (158.3129, 30)
  line L3 (19.0955, 10) -> (19.0955, 30)
  line L4 (144.3129, 10) -> (19.0955, 10)
  line L5 (144.3129, -14.7208) -> (144.3129, 10)
  line L6 (152.982, 24.7645) -> (152.982, 13.2652)
  line L7 (84.482, 17.0149) -> (152.982, 17.0149)
  line L8 (84.482, 21.0149) -> (84.482, 17.0149)
  line L9 (152.982, 21.0149) -> (84.482, 21.0149)
  line L10 (152.982, 17.0149) -> (152.982, 21.0149)
  line L11 (84.482, 21.0149) -> (152.982, 17.0149)
  line L12 (152.982, 21.0149) -> (84.482, 17.0149)
  arc A1 centre (148.3129, 16.807) radius 10 clockwise from (158.3129, 16.807) to (155.0188, 9.3887)
  arc A2 centre (176.8129, -14.7208) radius 32.5 clockwise from (144.3129, -14.7208) to (155.0188, 9.3887)
  point P17 (118.732, 19.0149)
  point P13 (152.982, 17.0149)
  point P14 (84.482, 17.0149)
  point P15 (84.482, 21.0149)
  horizontal L7
  perpendicular L7 L8
  parallel L7 L9
  parallel L8 L10
  coincident L11 P17
  coincident L12 P17
  coincident L6 P13
  dimension "d467" distance P14 P15 = 4
split "Split20"
remove_body "RemoveBody14"
remove_body "RemoveBody15"
sketch "Sketch58" plane through (15, 0, 0) normal (1, 0, 0) x axis (0, 1, 0)
  line L1 (152.982, 21.0149) -> (84.482, 21.0149)
  line L2 (152.982, 17.0149) -> (152.982, 21.0149)
  line L3 (84.482, 17.0149) -> (152.982, 17.0149)
  line L4 (84.482, 21.0149) -> (84.482, 17.0149)
  line L5 (158.3129, 30) -> (158.3129, 16.807)
  line L6 (19.0955, 30) -> (158.3129, 30)
  line L7 (19.0955, 10) -> (19.0955, 30)
  line L8 (144.3129, 10) -> (19.0955, 10)
  line L9 (144.3129, -14.7208) -> (144.3129, 10)
  line L10 (152.982, 29) -> (152.982, 21.0149)
  line L11 (156.982, 29) -> (152.982, 29)
  line L12 (156.982, 17) -> (156.982, 29)
  line L13 (152.982, 17.0149) -> (156.982, 17)
  arc A1 centre (148.3129, 16.807) radius 10 clockwise from (158.3129, 16.807) to (155.0188, 9.3887)
  arc A2 centre (176.8129, -14.7208) radius 32.5 clockwise from (144.3129, -14.7208) to (155.0188, 9.3887)
  point P3 (152.982, 21.0149)
  point P15 (152.982, 21.0149)
  point P4 (152.982, 17.0149)
  point P19 (152.982, 17.0149)
  point P16 (152.982, 29)
  point P17 (156.982, 29)
  coincident P3 P15
  perpendicular L1 L10
  perpendicular L10 L11
  perpendicular L1 L12
  coincident P4 P19
  dimension "d468" distance P16 P17 = 4
extrude "Extrude52" cut sketch "Sketch58" profile of L2 L10 L11 L12 L13 against normal blind 60
delete_face "DeleteFace42" TranslateX 0
delete_face "DeleteFace43"
move_face "MoveFace61" TranslateX 0 TranslateY -1 TranslateZ 0
move_face "MoveFace62" TranslateX 0 TranslateY 0 TranslateZ -0.5
move_face "MoveFace63" TranslateY 0 TranslateZ 0.5
move_face "MoveFace64" TranslateX 0 TranslateY 0 TranslateZ -2
fillet "Fillet69" radius 1.5
fillet "Fillet70" radius 3
fillet "Fillet71" radius 1
fillet "Fillet72" radius 1.5
fillet "Fillet73" radius 2
fillet "Fillet74" radius 0.5
chamfer "Chamfer13" distance 0.5
chamfer "Chamfer14" distance 1
chamfer "Chamfer15" distance 1
chamfer "Chamfer16" distance 2
chamfer "Chamfer17" distance 2
chamfer "Chamfer18" distance 2
remove_body "RemoveBody16"
sketch "Sketch59" plane through (0, 158.3129, 0) normal (0, 1, 0) x axis (-1, 0, 0)
  line L1 (14, 30) -> (14.5, 29.5)
  line L2 (-14, 30) -> (14, 30)
  line L3 (-14.5, 29.5) -> (-14, 30)
  line L4 (-14.5, 16.807) -> (-14.5, 29.5)
  line L5 (-9.9224, 16.807) -> (-14.5, 16.807)
  line L6 (14.5, 16.807) -> (9.6903, 16.807)
  line L7 (14.5, 29.5) -> (14.5, 16.807)
  line L8 (-10.6845, 30) -> (10.4524, 30)
  line L9 (-10.6845, 8.0563) -> (-10.6845, 30)
  line L10 (10.4524, 8.0563) -> (-10.6845, 8.0563)
  line L11 (10.4524, 30) -> (10.4524, 8.0563)
  line L12 (-10.6845, 8.0563) -> (10.4524, 30)
  line L13 (10.4524, 8.0563) -> (-10.6845, 30)
  line L14 (-19.2321, 32) -> (19, 32)
  line L15 (-19.2321, 6.0563) -> (-19.2321, 32)
  line L16 (19, 6.0563) -> (-19.2321, 6.0563)
  line L17 (19, 32) -> (19, 6.0563)
  line L18 (-19.2321, 6.0563) -> (19, 32)
  line L19 (19, 6.0563) -> (-19.2321, 32)
  line L20 (19, 14.1299) -> (-19.2321, 14.1299)
  arc A1 centre (-0.116, 19.0281) radius 10.0547 clockwise from (-9.9224, 16.807) to (9.6903, 16.807)
  point P15 (-0.116, 19.0281)
  point P11 (10.4524, 30)
  point P9 (-0.116, 19.0281)
  point P20 (-0.116, 19.0281)
  point P22 (-19.2321, 14.1299)
  point P23 (19, 14.1299)
  horizontal L8
  perpendicular L8 L9
  parallel L8 L10
  parallel L9 L11
  coincident L12 P15
  coincident L13 P15
  coincident L2 P11
  coincident P9 P15
  horizontal L14
  perpendicular L14 L15
  parallel L14 L16
  parallel L15 L17
  coincident L18 P20
  coincident L19 P20
  coincident P15 P20
  coincident L15 P22
  coincident L17 P23
  perpendicular L17 L20
extrude "Extrude53" cut sketch "Sketch59" profile of L1 L2 L3 L4 L5 L6 L7 L8 L9 L11 L14 L15 L17 L20 against normal blind 160
move_face "MoveFace65"
move_face "MoveFace66"
delete_face "DeleteFace44"
delete_face "DeleteFace45"
chamfer "Chamfer19" distance 2
fillet "Fillet75" radius 1
delete_face "DeleteFace46"
chamfer "Chamfer20" distance 0.5
chamfer "Chamfer21" distance 0.5
chamfer "Chamfer22" distance 0.5
path_pattern "PathPattern1" PathPatternDelta 9.314
sketch "Sketch60" plane through (12.7981, 0, 0) normal (1, 0, 0) x axis (0, 1, 0)
  line L1 (182.0185, 21.6362) -> (189.1436, 21.6343)
  line L2 (182.8653, 20.0686) -> (182.9049, 20.5623)
  curve K1 (184.5061, 14.8028) -> (182.8653, 20.0686)
  curve K2 (188.296, 20.0672) -> (186.6525, 14.8022)
  line L3 (188.2567, 20.5609) -> (188.296, 20.0672)
  line L4 (117, 21.6343) -> (189.1436, 21.6343)
  line L5 (117, 25) -> (117, 21.6343)
  line L6 (189.1436, 25) -> (117, 25)
  line L7 (189.1436, 21.6343) -> (189.1436, 25)
  arc A1 centre (181.9081, 20.6423) radius 1 clockwise from (182.0185, 21.6362) to (182.9049, 20.5623)
  arc A2 centre (185.5895, 53.7877) radius 39 clockwise from (186.6525, 14.8022) to (184.5061, 14.8028)
  arc A3 centre (189.2535, 20.6404) radius 1 clockwise from (188.2567, 20.5609) to (189.1436, 21.6343)
  point P2 (189.1436, 21.6343)
  point P13 (189.1436, 21.6343)
  horizontal L4
  vertical L5
  horizontal L6
  vertical L7
  coincident P2 P13
extrude "Extrude54" new body sketch "Sketch60" profile of L1 A1 L4 L5 L6 L7 against normal blind 3
combine "Combine48"
delete_face "DeleteFace47"
delete_face "DeleteFace48"
delete_face "DeleteFace49"
split "Split21"
split "Split22"
combine "Combine49"
move "Move43"
move "Move2"
move "Move44"
delete_face "DeleteFace50"
move_face "MoveFace67"
delete_face "DeleteFace51"
move_face "MoveFace68"
move_face "MoveFace69"
move_face "MoveFace70"
extrude "Extrude55" new body of existing geometry blind 2
combine "Combine50"
move_face "MoveFace71"
move_face "MoveFace3" TranslateX 0 TranslateY -15 TranslateZ 0
move_face "MoveFace4" TranslateX 0 TranslateY -10 TranslateZ 0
